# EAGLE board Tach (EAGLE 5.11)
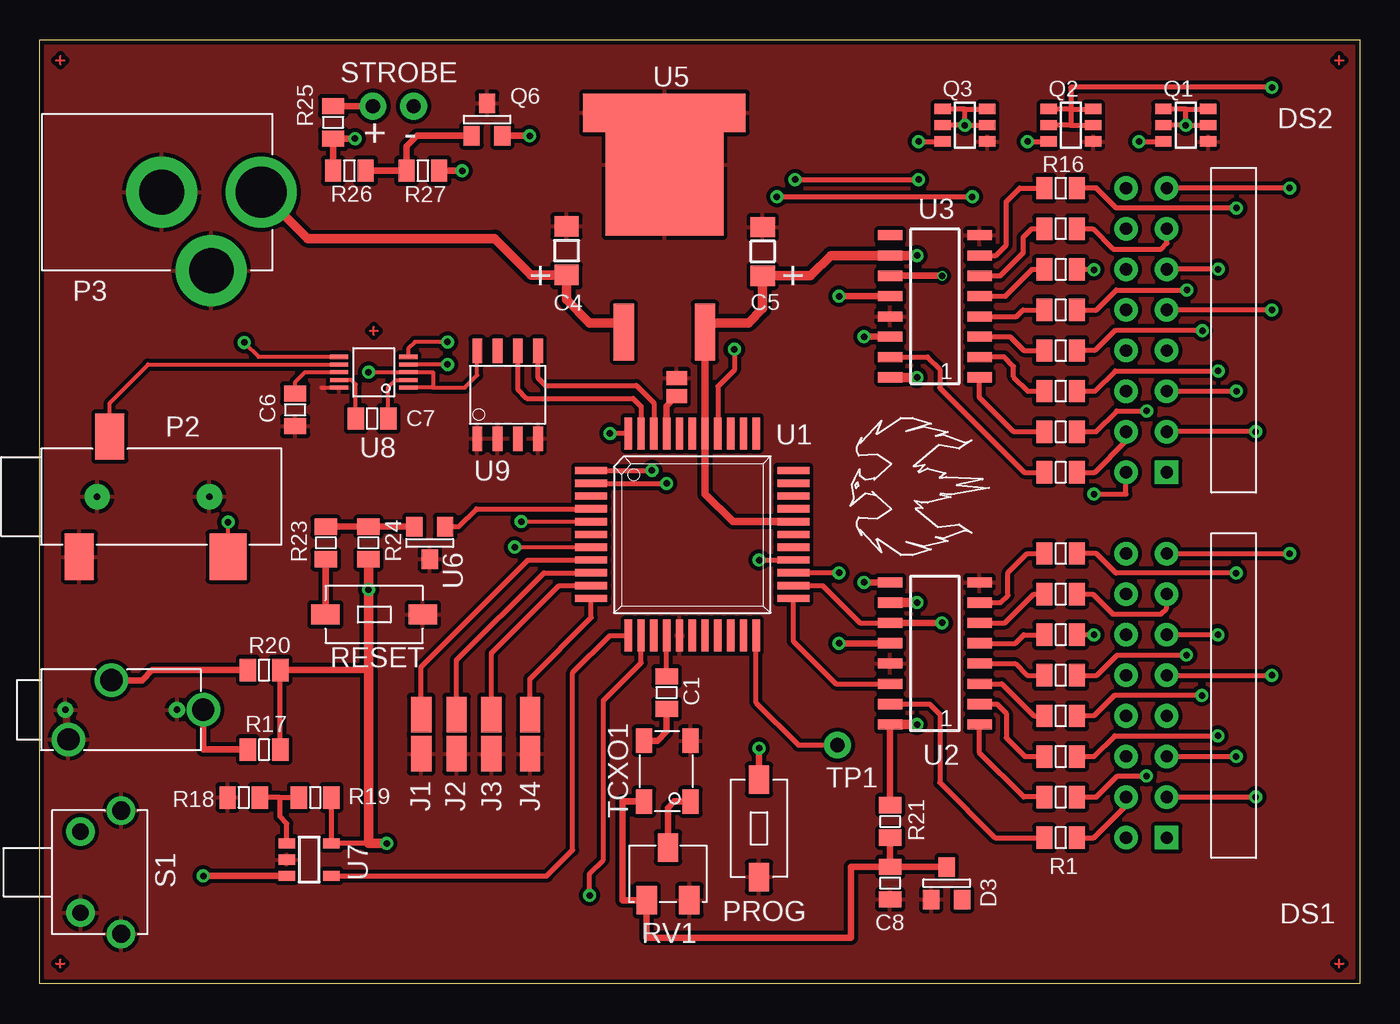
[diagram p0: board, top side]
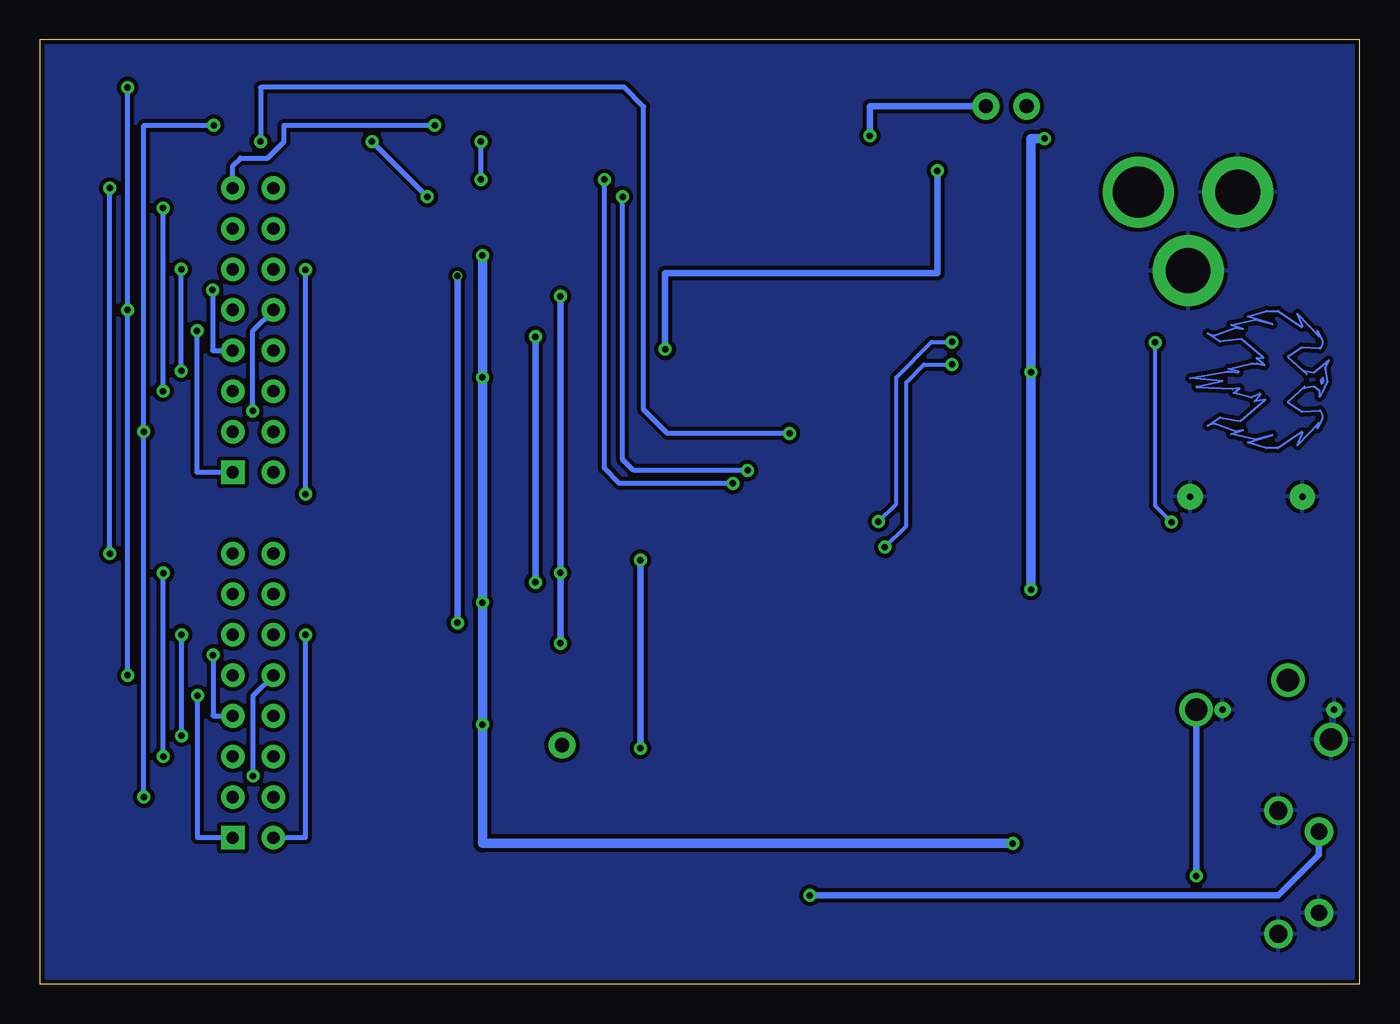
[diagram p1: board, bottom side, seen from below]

Size 82.55 x 59.05 mm. Coordinates in mm from the lower left corner, seen from the top.
Outline: 0,0 0,59.05 82.55,59.05 82.55,0 0,0
Copper layers (1*16): Top 0.035mm / dielectric 1.5mm / Bottom 0.035mm
Design rules "default *": minimum track width 10mil, minimum drill 1mil, track to track 8mil, track to pad 8mil, pad to pad 8mil, via to via 8mil, smd to smd 8mil, copper to edge 0mil, drill to drill 8mil, minimum pad ring 0mil, minimum via ring 0mil, stop-mask expansion 4mil, vias tented up to drill 20mil, thermal gap 10mil

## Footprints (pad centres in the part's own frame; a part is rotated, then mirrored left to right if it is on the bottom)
C0805 = smd 1.016 x 1.397: P$1 -1.016,0; P$2 1.016,0
C1206 = smd 1.524 x 1.27: P$1 0,1.524; P$2 0,-1.524
SOT23 = smd 1.016 x 1.219: 1 -0.94,1.016; 2 0.991,1.016; 3 0.025,-1.016
DIP16_RA = drill 0.762 pad 1.473 square: P$1 -8.89,-1.27 | drill 0.762 pad 1.473 round: P$2 -6.35,-1.27; P$3 -3.81,-1.27; P$4 -1.27,-1.27; P$5 1.27,-1.27; P$6 3.81,-1.27; P$7 6.35,-1.27; P$8 8.89,-1.27; P$9 8.89,1.27; P$10 6.35,1.27; P$11 3.81,1.27; P$12 1.27,1.27; P$13 -1.27,1.27; P$14 -3.81,1.27; P$15 -6.35,1.27; P$16 -8.89,1.27
SM_JUMP = smd 2.235 x 1.27: P$1 1.219,0; P$2 -1.219,0
TCXO_TX-T = smd 1.524 x 1.016: P$1 -1.905,1.448; P$2 -1.905,-1.448; P$3 1.905,-1.448; P$4 1.905,1.448
TP = drill 0.889 pad 1.676 round: P$1 0,0
SMJUMP-S = smd 0.889 x 1.27: P$1 0.559,0; P$2 -0.559,0
2.5MMSTEREORA = drill 0.406 pad 1.016 round: P$1 3.493,0; P$2 -3.493,0 | drill 1.397 pad 2.032 round: P$3 -3.302,-1.854; P$4 5.131,0; P$5 -0.61,1.854
3.5MMST_RA_SMT-3 = smd 1.803 x 2.896: P$1 5.131,3.759; P$2 3.226,-3.759 | smd 2.311 x 2.896: P$3 -4.166,3.759 | drill 0.406 pad 1.587 round: P$5 -2.997,0; P$6 4.013,0
2.5MMRA_PWR = drill 2.794 pad 4.445 round: P$1 0,0; P$3 3.099,-4.902 | drill 3.175 pad 4.445 round: P$2 6.223,0
SPST3X6 = smd 1.778 x 1.27: P$1 3.048,0; P$2 -3.048,0
SOT6 = smd 1.016 x 0.635: P$1 1.397,-1.016; P$2 1.397,0; P$3 -1.397,0; P$4 -1.397,-1.016; P$5 -1.397,1.016; P$6 1.397,1.016
SMPOTMUL = smd 1.27 x 1.778: P$1 0,-1.651; P$2 1.333,1.651; P$3 -1.333,1.651
TACTRA = drill 1.143 pad 1.778 round: P$1 1.346,-3.861; P$2 1.346,3.861 | drill 1.016 pad 1.778 round: P$3 -1.194,2.54; P$4 -1.194,-2.54
QFP-44 = smd 0.457 x 2.007: 1 -4,-6.325; 2 -3.2,-6.325; 3 -2.4,-6.325; 4 -1.6,-6.325; 5 -0.8,-6.325; 6 0,-6.325; 7 0.8,-6.325; 8 1.6,-6.325; 9 2.4,-6.325; 10 3.2,-6.325; 11 4,-6.325; 23 4,6.325; 24 3.2,6.325; 25 2.4,6.325; 26 1.6,6.325; 27 0.8,6.325; 28 0,6.325; 29 -0.8,6.325; 30 -1.6,6.325; 31 -2.4,6.325; 32 -3.2,6.325; 33 -4,6.325 | smd 2.007 x 0.457: 12 6.325,-4; 13 6.325,-3.2; 14 6.325,-2.4; 15 6.325,-1.6; 16 6.325,-0.8; 17 6.325,0; 18 6.325,0.8; 19 6.325,1.6; 20 6.325,2.4; 21 6.325,3.2; 22 6.325,4; 34 -6.325,4; 35 -6.325,3.2; 36 -6.325,2.4; 37 -6.325,1.6; 38 -6.325,0.8; 39 -6.325,0; 40 -6.325,-0.8; 41 -6.325,-1.6; 42 -6.325,-2.4; 43 -6.325,-3.2; 44 -6.325,-4
SO16 = smd 1.524 x 0.635: P$1 -2.794,0.635; P$2 2.794,0.635; P$3 2.794,-0.635; P$4 -2.794,-0.635; P$5 2.794,1.905; P$6 -2.794,1.905; P$7 2.794,-1.905; P$8 -2.794,-1.905; P$9 2.794,-3.175; P$10 -2.794,-3.175; P$11 -2.794,3.175; P$12 2.794,3.175; P$13 -2.794,4.445; P$14 2.794,4.445; P$15 2.794,-4.445; P$16 -2.794,-4.445
TO263 = smd 7.366 x 8.89: P$1 0,0 | smd 1.27 x 3.556: P$2 -2.54,-10.477; P$3 2.54,-10.477 | smd 10.16 x 2.413: P$4 0,3.239
SOT23-5 = smd 1.016 x 0.635: 1 -1.397,1.016; 2 -1.397,0; 3 -1.397,-1.016; 4 1.397,-1.016; 5 1.397,1.016
10UMAX = smd 0.254 x 1.143: P$1 -0.965,-2.159; P$2 -0.483,-2.159; P$3 0.483,-2.159; P$4 0.965,-2.159; P$5 0.965,2.159; P$6 0.483,2.159; P$7 -0.483,2.159; P$8 -0.965,2.159; P$9 0,-2.159; P$10 0,2.159
SO-8 = smd 0.61 x 1.524: 1 -1.27,-2.743; 2 0,-2.743; 3 1.27,-2.743; 4 2.54,-2.743; 5 2.54,2.743; 6 1.27,2.743; 7 0,2.743; 8 -1.27,2.743

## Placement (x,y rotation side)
C1  [C0805]  39.2,18.22 90 top
C4  [C1206]  32.94,45.87 180 top
C5  [C1206]  45.21,45.82 180 top
C6  [C0805]  15.96,35.92 90 top
C7  [C0805]  20.78,35.37 0 top
C8  [C0805]  53.19,6.3 90 top
D3  [SOT23]  56.74,6.3 180 top
E$1  [DIP16_RA]  69.22,40.89 90 top
E$2  [DIP16_RA]  69.22,18.03 90 top
E$3  [SM_JUMP]  23.85,15.62 90 top
E$4  [FUDUCIAL]  1.27,57.78 0 top
E$5  [SM_JUMP]  26.06,15.62 90 top
E$6  [SM_JUMP]  28.24,15.62 90 top
E$7  [TCXO_TX-T]  39.24,13.31 90 top
E$8  [SM_JUMP]  30.66,15.62 90 top
E$9  [TP]  20.83,54.91 0 top
E$10  [TP]  23.37,54.91 0 top
E$11  [PHOENIX_LOGO]  53.85,31.11 90 top
E$12  [PHOENIX_LOGO_CU]  5.08,37.81 270 bottom
E$13  [FUDUCIAL]  81.28,1.27 0 top
E$14  [TP]  49.89,14.94 0 top
E$15  [FUDUCIAL]  20.88,40.86 0 top
E$16  [FUDUCIAL]  1.27,1.27 0 top
E$17  [FUDUCIAL]  81.28,57.78 0 top
E$18  [SMJUMP-S]  39.83,37.34 90 top
E$19  [2.5MMSTEREORA]  5.08,17.14 0 top
P2  [3.5MMST_RA_SMT-3]  7.59,30.48 180 top
P3  [2.5MMRA_PWR]  7.62,49.53 0 top
PROG  [SPST3X6]  44.98,9.73 270 top
Q1  [SOT6]  71.68,53.72 0 top
Q2  [SOT6]  64.49,53.72 0 top
Q3  [SOT6]  57.86,53.72 0 top
Q6  [SOT23]  27.99,54.08 180 top
R1  [C0805]  63.86,9.14 0 top
R2  [C0805]  63.86,11.68 0 top
R3  [C0805]  63.86,14.22 0 top
R4  [C0805]  63.86,16.76 0 top
R5  [C0805]  63.86,19.3 0 top
R6  [C0805]  63.86,21.84 0 top
R7  [C0805]  63.86,24.38 0 top
R8  [C0805]  63.86,26.92 0 top
R9  [C0805]  63.86,32 0 top
R10  [C0805]  63.86,34.54 0 top
R11  [C0805]  63.86,37.08 0 top
R12  [C0805]  63.86,39.62 0 top
R13  [C0805]  63.86,42.16 0 top
R14  [C0805]  63.86,44.7 0 top
R15  [C0805]  63.86,47.24 0 top
R16  [C0805]  63.86,49.78 0 top
R17  [C0805]  14.02,14.66 0 top
R18  [C0805]  12.75,11.66 0 top
R19  [C0805]  17.22,11.66 0 top
R20  [C0805]  14.02,19.63 0 top
R21  [C0805]  53.19,10.16 90 top
R23  [C0805]  17.88,27.58 90 top
R24  [C0805]  20.55,27.58 270 top
R25  [C0805]  18.34,53.9 90 top
R26  [C0805]  19.35,50.88 180 top
R27  [C0805]  23.95,50.88 0 top
RESET  [SPST3X6]  20.9,23.11 0 top
RV1  [SMPOTMUL]  39.29,6.88 180 top
S1  [TACTRA]  3.73,6.99 0 top
U1  [QFP-44]  40.81,28.12 270 top
U2  [SO16]  55.98,20.68 180 top
U3  [SO16]  55.98,42.39 180 top
U5  [TO263]  39.07,51.26 0 top
U6  [SOT23]  24.36,27.58 0 top
U7  [SOT23-5]  16.84,7.77 0 top
U8  [10UMAX]  20.88,38.27 90 top
U9  [SO-8]  28.63,36.86 0 top

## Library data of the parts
C1 C4-C8 D3 E$4 E$7 E$13 E$15-E$17 Q1-Q3 Q6 R1-R21 R23-R27 U2 U3 U6 U7 = RF
E$1 E$2 = pinhead
E$3 E$5 E$6 E$8-E$12 E$14 E$18 E$19 P2 P3 PROG RESET RV1 S1 = WJC
U1 U5 U8 U9 = SMD-IC

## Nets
3V3: C8.P$2 D3.3 E$7.P$1 R21.P$1 RV1.P$2
$GND: C4.P$2 C5.P$2 C6.P$1 C8.P$1 D3.2 E$3.P$2 E$5.P$2 E$6.P$2 E$7.P$3 E$8.P$2 E$18.P$1 E$19.P$1 E$19.P$2 E$19.P$3 P2.P$1 P2.P$5 P2.P$6 P3.P$1 P3.P$3 PROG.P$1 Q1.P$1 Q2.P$1 Q3.P$1 Q6.3 R18.P$1 RESET.P$1 RV1.P$3 S1.P$1 S1.P$2 S1.P$4 U1.16 U2.P$2 U2.P$16 U3.P$2 U3.P$16 U5.P$1 U5.P$4 U6.3 U7.2 U8.P$8 U9.1 U9.2 U9.4
$VCC: C5.P$1 R17.P$2 R19.P$2 R20.P$2 R21.P$2 R24.P$2 R25.P$1 R26.P$2 U1.29 U1.38 U2.P$9 U2.P$14 U3.P$9 U3.P$14 U5.P$3 U7.5 U8.P$1 U8.P$9 U9.8
S$1: U1.3
S$2: C6.P$2 U8.P$10
S$3: C4.P$1 P3.P$2 U5.P$2
S$4: C7.P$1 U8.P$7
S$5: C7.P$2 U8.P$2
S$6: P2.P$2 U8.P$6
S$7: U1.7 U8.P$3
S$8: U1.5 U8.P$4
S$9: C1.P$1 E$7.P$4
S$10: U1.12 U7.4
S$11: Q3.P$4 U1.2
S$12: E$19.P$5 R20.P$1
S$13: E$3.P$1 U1.8
S$14: E$5.P$1 U1.9
S$15: E$6.P$1 U1.10
S$16: E$8.P$1 U1.11
S$17: C1.P$2 U1.15
S$18: Q2.P$4 U1.1
S$19: Q1.P$4 U1.44
S$20: U1.4 U6.2
S$21: PROG.P$2 U1.26
S$22: R23.P$2 R24.P$1 U6.1
S$23: R23.P$1 RESET.P$2
S$24: U1.23 U2.P$5
S$25: U1.24 U2.P$7 U3.P$7
S$26: U1.25 U2.P$3 U3.P$3
S$27: U1.42 U9.5
S$28: E$2.P$15 R1.P$2
S$29: E$2.P$12 R2.P$2
S$30: U2.P$15 U3.P$5
S$31: R1.P$1 U2.P$12
S$32: R2.P$1 U2.P$13
S$33: R3.P$1 U2.P$11
S$34: R4.P$1 U2.P$6
S$35: R5.P$1 U2.P$1
S$36: R6.P$1 U2.P$4
S$37: R7.P$1 U2.P$8
S$38: R8.P$1 U2.P$10
S$39: R9.P$1 U3.P$12
S$40: U1.43 U9.6
S$41: R10.P$1 U3.P$13
S$42: R11.P$1 U3.P$11
S$43: R12.P$1 U3.P$6
S$44: R13.P$1 U3.P$1
S$45: R14.P$1 U3.P$4
S$46: R15.P$1 U3.P$8
S$47: R16.P$1 U3.P$10
S$48: E$2.P$6 R3.P$2
S$49: E$2.P$1 R4.P$2
S$50: E$2.P$4 R5.P$2
S$51: E$2.P$16 R6.P$2
S$52: E$2.P$7 R7.P$2
S$53: E$2.P$3 R8.P$2
S$54: E$10.P$1 Q6.1
S$55: E$1.P$5 E$2.P$5 Q2.P$2 Q2.P$3 Q2.P$5 Q2.P$6
S$56: E$1.P$2 E$2.P$2 Q1.P$2 Q1.P$3 Q1.P$5 Q1.P$6
S$57: E$18.P$2 U1.41
S$58: E$1.P$8 E$2.P$8 Q3.P$2 Q3.P$3 Q3.P$5 Q3.P$6
S$59: E$19.P$4 R17.P$1 U7.3
S$62: E$1.P$3 R16.P$2
S$63: E$1.P$7 R15.P$2
S$64: E$1.P$16 R14.P$2
S$65: E$1.P$15 R9.P$2
S$66: E$1.P$12 R10.P$2
S$67: E$1.P$6 R11.P$2
S$68: E$1.P$1 R12.P$2
S$69: E$1.P$4 R13.P$2
S$71: E$9.P$1 R25.P$2
S$72: R27.P$2 U1.37
S$73: Q6.2 R26.P$1 R27.P$1
S$74: R18.P$2 R19.P$1 U7.1
S$78: E$14.P$1 U1.22
S$79: S1.P$3 U1.13
S$80: P2.P$3 U8.P$5
S$85: E$7.P$2 RV1.P$1

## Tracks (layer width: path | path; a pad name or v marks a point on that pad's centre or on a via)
3V3
  Top 0.406: E$7.P$1 36.45,11.4 36.45,5.23 RV1.P$2 37.96,2.9 50.72,2.9 50.72,7.32 C8.P$2 | C8.P$2 R21.P$1 | C8.P$2 D3.3
$GND
  Top 0.254: 17.6,37.3 U8.P$8
  pour Top (isolate 0.254): 0.38,0.38 0.38,58.67 82.17,58.67 82.17,0.38
  pour Bottom (isolate 0.254): 0.38,0.38 0.38,58.67 82.17,58.67 82.17,0.38
$VCC  (via drill 0.41 pad 0.81)
  Top 0.254: 24.59,37.3 U8.P$1 | 24.59,37.3 24.59,38.27 U8.P$9 v20.55,38.27 | U9.8 27.36,38.09 26.57,37.3 24.59,37.3
  Top 0.305: 20.55,8.79 U7.5 R19.P$2 | R17.P$2 R20.P$2
  Top 0.406: R26.P$2 R25.P$1 v19.71,52.88 | U2.P$14 R21.P$2 | R20.P$2 20.55,19.63
  Top 0.457: U1.29 43.34,28.92 41.6,30.66 U1.38 U5.P$3
  Top 0.61: U5.P$3 41.6,41.35 44.32,41.35 45.21,42.24 C5.P$1 48.21,44.3 49.48,45.57 U3.P$9 v54.86,45.57 | v54.86,37.95 U3.P$14 | v54.86,23.85 U2.P$9 | v54.86,16.23 U2.P$14 | R24.P$2 v20.55,24.66 20.55,19.63 20.55,8.79 v21.69,8.79
  Bottom 0.61: v54.86,45.57 v54.86,37.95 v54.86,23.85 v54.86,16.23 54.86,8.79 v21.69,8.79 | v19.71,52.88 20.55,52.88 v20.55,38.27 v20.55,24.66
S$2
  Top 0.254: C6.P$2 15.96,37.66 16.57,38.27 U8.P$10
S$3
  Top 0.61: U5.P$2 36.51,41.35 34.39,41.35 32.94,42.8 C4.P$1 30.73,44.35 28.45,46.63 16.74,46.63 P3.P$2
S$4
  Top 0.254: U8.P$7 19.48,37.78 19.76,37.5 C7.P$1
S$5
  Top 0.254: C7.P$2 21.79,37.34 22.24,37.78 U8.P$2
S$6
  Top 0.254: U8.P$6 6.77,38.75 4.37,36.35 P2.P$2
S$7  (via drill 0.41 pad 0.81)
  Top 0.254: v29.69,27.32 U1.7 | v25.49,38.75 U8.P$3
  Bottom 0.254: v29.69,27.32 28.36,28.65 28.36,37.63 27.24,38.75 v25.49,38.75
S$8  (via drill 0.41 pad 0.81)
  Top 0.254: v30.1,28.92 U1.5 | v25.49,40.16 23.46,40.16 23.04,39.74 U8.P$4
  Bottom 0.254: v30.1,28.92 28.98,30.04 28.98,37.95 26.77,40.16 v25.49,40.16
S$9
  Top 0.406: E$7.P$4 38.62,15.21 39.2,15.8 C1.P$1
S$10
  Top 0.305: U1.12 35.65,21.79 33.33,19.47 33.33,8.38 31.7,6.76 U7.4
S$11  (via drill 0.41 pad 0.81)
  Top 0.305: v54.97,52.7 Q3.P$4 | v47.24,50.32 v54.97,50.32 | U1.2 v39.2,31.32
  Bottom 0.305: v54.97,50.32 v54.97,52.7 | v39.2,31.32 46.3,31.32 47.24,32.26 v47.24,50.32
S$12
  Top 0.406: R20.P$1 7.54,19.63 7.04,19.63 6.4,19 E$19.P$5
S$13
  Top 0.305: E$3.P$1 23.85,19.84 30.53,26.52 U1.8
S$14
  Top 0.305: E$5.P$1 26.06,20.26 31.52,25.72 U1.9
S$15
  Top 0.305: E$6.P$1 28.25,20.69 32.47,24.92 U1.10
S$16
  Top 0.305: E$8.P$1 30.66,19.09 34.48,22.91 U1.11
S$17
  Top 0.305: C1.P$2 U1.15
S$18  (via drill 0.41 pad 0.81)
  Top 0.305: v61.77,52.7 Q2.P$4 | v46.1,49.25 v58.32,49.25 | U1.1 v38.28,32.12
  Bottom 0.305: v58.32,49.25 v61.77,52.7 | v38.28,32.12 45.41,32.12 46.1,32.8 v46.1,49.25
S$19  (via drill 0.41 pad 0.81)
  Top 0.305: v68.76,52.7 Q1.P$4 | U1.44 v35.66,34.44
  Bottom 0.305: v68.76,52.7 68.76,56.08 45.97,56.08 44.78,54.89 44.78,35.92 43.31,34.44 v35.66,34.44
S$20
  Top 0.305: U1.4 27.3,29.72 26.19,28.6 U6.2
S$21  (via drill 0.41 pad 0.81)
  Top 0.305: v44.98,26.52 U1.26
  Top 0.406: PROG.P$2 v44.98,14.74
  Bottom 0.406: v44.98,14.74 v44.98,26.52
S$22
  Top 0.406: R23.P$2 R24.P$1 U6.1
S$23
  Top 0.406: RESET.P$2 17.86,26.54 R23.P$1
S$24
  Top 0.305: U2.P$5 49.78,18.77 47.13,21.43 U1.23
S$25  (via drill 0.41 pad 0.61, 0.41 pad 0.81)
  Top 0.305: U2.P$7 51.3,22.58 48.96,24.92 U1.24
  Top 0.406: U2.P$7 v56.44,22.58 | v56.44,44.3 U3.P$7
  Bottom 0.406: v56.44,22.58 v56.44,44.3
S$26  (via drill 0.41 pad 0.81)
  Top 0.305: v49.99,25.72 U1.25
  Top 0.406: v49.99,21.31 U2.P$3 | v49.99,43.03 U3.P$3
  Bottom 0.406: v49.99,21.31 v49.99,25.72 v49.99,43.03
S$27
  Top 0.305: U1.42 38.41,36.35 37.31,37.44 31.62,37.44 31.17,37.9 U9.5
S$28
  Top 0.305: R1.P$2 65.94,9.14 67.94,11.15 E$2.P$15
S$29  (via drill 0.41 pad 0.81)
  Top 0.305: R2.P$2 66.09,11.68 67.41,13.01 v69.22,13.01
  Bottom 0.305: v69.22,13.01 69.22,18.03 E$2.P$12
S$30  (via drill 0.41 pad 0.81)
  Top 0.406: U2.P$15 v51.56,25.12 | v51.56,40.49 U3.P$5
  Bottom 0.406: v51.56,25.12 v51.56,40.49
S$31
  Top 0.305: U2.P$12 55.65,17.5 56.29,16.87 56.29,12.6 59.74,9.14 R1.P$1
S$32
  Top 0.305: U2.P$13 58.78,14.45 61.54,11.68 R2.P$1
S$33
  Top 0.305: U2.P$11 59.87,17.5 60.45,16.92 60.45,15.39 61.62,14.22 R3.P$1
S$34
  Top 0.305: U2.P$6 60.17,18.77 62.18,16.76 R4.P$1
S$35
  Top 0.305: U2.P$1 61.01,20.04 61.75,19.3 R5.P$1
S$36
  Top 0.305: U2.P$4 61.01,21.31 61.54,21.84 R6.P$1
S$37
  Top 0.305: U2.P$8 60.38,22.58 62.18,24.38 R7.P$1
S$38
  Top 0.305: U2.P$10 60.1,23.85 60.55,24.31 60.55,25.73 61.75,26.92 R8.P$1
S$39
  Top 0.305: U3.P$12 55.52,39.22 56.29,38.46 56.29,37.29 61.57,32 R9.P$1
S$40
  Top 0.305: U9.6 29.9,37.19 30.45,36.63 37.11,36.63 37.6,36.13 U1.43
S$41
  Top 0.305: U3.P$13 58.78,36.68 60.91,34.54 R10.P$1
S$42
  Top 0.305: U3.P$11 60.33,39.22 60.91,38.63 60.91,37.97 61.8,37.08 R11.P$1
S$43
  Top 0.305: U3.P$6 60.68,40.49 61.54,39.62 R12.P$1
S$44
  Top 0.305: U3.P$1 61.09,41.76 61.49,42.16 R13.P$1
S$45
  Top 0.305: U3.P$4 60.4,43.03 62.08,44.7 R14.P$1
S$46
  Top 0.305: U3.P$8 60.07,44.3 61.52,45.74 61.52,46.71 62.05,47.24 R15.P$1
S$47
  Top 0.305: U3.P$10 59.79,45.57 60.45,46.23 60.45,48.95 61.29,49.78 R16.P$1
S$48  (via drill 0.41 pad 0.81)
  Top 0.305: R3.P$2 65.94,14.22 67.23,15.52 v73.69,15.52 | v73.69,21.84 E$2.P$6
  Bottom 0.305: v73.69,15.52 v73.69,21.84
S$49  (via drill 0.41 pad 0.81)
  Top 0.305: R4.P$2 65.94,16.76 67.21,18.03 v72.69,18.03
  Bottom 0.305: v72.69,18.03 72.69,9.14 E$2.P$1
S$50  (via drill 0.41 pad 0.81)
  Top 0.305: R5.P$2 66.12,19.3 67.39,20.57 v71.73,20.57
  Bottom 0.305: v71.73,20.57 71.73,16.76 E$2.P$4
S$51  (via drill 0.41 pad 0.81)
  Top 0.305: v65.94,21.84 R6.P$2
  Bottom 0.305: v65.94,21.84 65.94,9.14 E$2.P$16
S$52
  Top 0.305: R7.P$2 65.86,24.38 67.11,23.14 70.13,23.14 70.48,23.5 E$2.P$7
S$53  (via drill 0.41 pad 0.81)
  Top 0.305: R8.P$2 66.09,26.92 67.31,25.7 v74.83,25.7 | E$2.P$3 v74.83,14.22
  Bottom 0.305: v74.83,14.22 v74.83,25.7
S$54  (via drill 0.41 pad 0.81)
  Top 0.406: v30.63,53.06 Q6.1
  Bottom 0.406: E$10.P$1 30.63,54.91 v30.63,53.06
S$55  (via drill 0.41 pad 0.81)
  Top 0.305: 64.49,54.74 Q2.P$5 | 64.49,54.74 Q2.P$6 | 64.49,54.74 64.49,56.08 v77.06,56.08 | v77.06,42.16 E$1.P$5 | E$2.P$5 v77.06,19.3 | 64.49,53.72 Q2.P$3 | 64.49,53.72 Q2.P$2 | 64.49,54.74 64.49,53.72
  Bottom 0.305: v77.06,56.08 v77.06,42.16 v77.06,19.3
S$56  (via drill 0.41 pad 0.81)
  Top 0.305: v76.05,34.54 E$1.P$2 | E$2.P$2 v76.05,11.68 | 71.68,54.74 Q1.P$5 | 71.68,54.74 Q1.P$6 | v71.68,53.72 Q1.P$2 | v71.68,53.72 71.68,54.74 | v71.68,53.72 Q1.P$3
  Bottom 0.305: v76.05,11.68 v76.05,34.54 76.05,53.72 v71.68,53.72
S$57
  Top 0.406: U1.41 39.2,36.16 E$18.P$2
S$58  (via drill 0.41 pad 0.81)
  Top 0.305: v78.18,49.78 E$1.P$8 | E$2.P$8 v78.18,26.92 | v57.86,53.72 Q3.P$3 | v57.86,53.72 Q3.P$2 | 57.86,54.74 Q3.P$6 | v57.86,53.72 57.86,54.74 | 57.86,54.74 Q3.P$5
  Bottom 0.305: E$1.P$8 70.48,51.18 70,51.66 68.3,51.66 67.28,52.68 67.28,53.72 v57.86,53.72 | v78.18,26.92 v78.18,49.78
S$59  (via drill 0.41 pad 0.81)
  Top 0.406: R17.P$1 10.21,14.66 E$19.P$4 | 10.82,6.76 U7.3 v10.21,6.76
  Bottom 0.406: v10.21,6.76 E$19.P$4
S$62  (via drill 0.41 pad 0.81)
  Top 0.305: R16.P$2 66.09,49.78 67.33,48.54 v74.85,48.54 | E$1.P$3 v74.85,37.08
  Bottom 0.305: v74.85,37.08 v74.85,48.54
S$63
  Top 0.305: R15.P$2 65.86,47.24 67.13,45.97 70.16,45.97 70.51,46.33 70.51,47.22 E$1.P$7
S$64  (via drill 0.41 pad 0.81)
  Top 0.305: R14.P$2 65.05,44.68 v65.94,44.68 | v65.94,30.63 67.94,30.63 E$1.P$16
  Bottom 0.305: v65.94,30.63 v65.94,44.68
S$65
  Top 0.305: R9.P$2 65.99,32 67.94,33.96 E$1.P$15
S$66  (via drill 0.41 pad 0.81)
  Top 0.305: R10.P$2 66.06,34.54 67.36,35.84 v69.24,35.84
  Bottom 0.305: v69.24,35.84 69.24,40.87 E$1.P$12
S$67  (via drill 0.41 pad 0.81)
  Top 0.305: R11.P$2 65.99,37.08 67.26,38.35 v73.71,38.35 | v73.71,44.7 E$1.P$6
  Bottom 0.305: v73.71,38.35 v73.71,44.7
S$68  (via drill 0.41 pad 0.81)
  Top 0.305: R12.P$2 65.99,39.62 67.23,40.87 v72.72,40.87
  Bottom 0.305: v72.72,40.87 72.72,32 E$1.P$1
S$69  (via drill 0.41 pad 0.81)
  Top 0.305: R13.P$2 66.09,42.16 67.33,43.41 v71.75,43.41
  Bottom 0.305: v71.75,43.41 71.75,39.62 E$1.P$4
S$71
  Top 0.406: R25.P$2 E$9.P$1
S$72  (via drill 0.41 pad 0.81)
  Top 0.305: v43.43,39.7 43.43,38.41 42.41,37.38 U1.37
  Top 0.406: v26.42,50.88 R27.P$2
  Bottom 0.406: v26.42,50.88 26.42,44.48 43.43,44.48 v43.43,39.7
S$73
  Top 0.406: R26.P$1 R27.P$1 22.94,52.4 23.6,53.06 Q6.2
S$74
  Top 0.305: 15.04,11.66 R18.P$2 | 15.04,11.66 R19.P$1 | U7.1 15.44,10.03 15.01,10.46 15.01,11.63 15.04,11.66
S$78
  Top 0.305: E$14.P$1 47.45,14.94 44.81,17.58 U1.22
S$79  (via drill 0.41 pad 0.81)
  Top 0.305: v34.39,5.54 34.39,6.91 35.26,7.77 35.26,17.73 37.6,20.08 U1.13
  Bottom 0.406: v34.39,5.54 5.08,5.54 2.54,8.08 S1.P$3
S$80  (via drill 0.41 pad 0.81)
  Top 0.254: U8.P$5 13.68,39.23 v12.78,40.13 | P2.P$3 v11.76,28.89
  Bottom 0.254: v12.78,40.13 12.78,29.91 v11.76,28.89
S$85
  Top 0.406: RV1.P$1 39.29,11.02 39.67,11.4 E$7.P$2

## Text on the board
tPlace: STROBE | DS2 | + | - | + | + | TP1 | J1 | J2 | J3 | J4 | TCXO1 | DS1
tStop: MDU-485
